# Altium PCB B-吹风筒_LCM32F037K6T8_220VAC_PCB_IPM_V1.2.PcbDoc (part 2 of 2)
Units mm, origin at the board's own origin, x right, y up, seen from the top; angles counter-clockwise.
Board outline 42.33 x 117.1 mm, 2 copper layers (TopLayer, BottomLayer); 131 components, 93 nets, 324 pads, 143 vias.
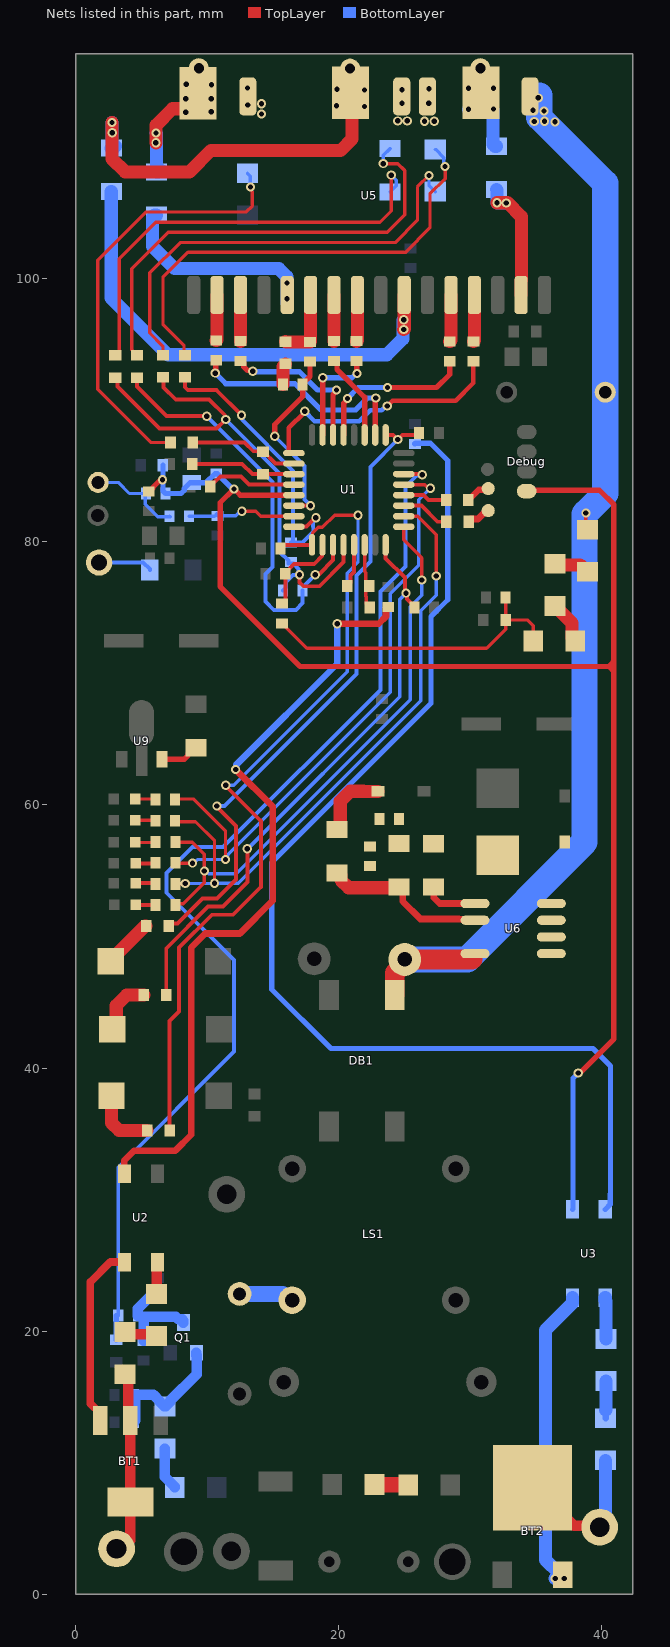
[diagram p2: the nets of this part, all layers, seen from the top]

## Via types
v1: diameter 0.7, hole 0.4, TopLayer to BottomLayer, tented both sides, 133 vias
v2: diameter 0.7, hole 0.4, TopLayer to BottomLayer, 10 vias

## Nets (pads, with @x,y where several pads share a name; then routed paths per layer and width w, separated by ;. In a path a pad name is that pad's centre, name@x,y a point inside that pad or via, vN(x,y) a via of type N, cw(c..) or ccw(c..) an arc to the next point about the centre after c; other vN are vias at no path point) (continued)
HV: C12.2 DB1.2 EC1.1 R44.2 U5.17 U6.4 | length 86.3
  TopLayer w0.254: v1(38.775,82.2) 38.775,81.05 R44.2@38.9,80.925
  TopLayer w1.5: DB1.2@24.25,45.55 24.25,47.225 25.006,47.981 EC1.1@25.006,48.251 30.126,48.251 30.15,48.275
  BottomLayer w2: EC1.1@25.006,48.251 29.751,48.251 38.675,57.175 38.675,82.1 v1(38.775,82.2) 40.25,83.675 C12.2@40.25,91.375 40.25,107.25 35.225,112.275 v1@35.225,113.925
  other v1: 36.425,111.925 34.85,111.95 35.625,111.975 35.6,112.75 34.75,112.8 35.15,113.75
IRbus: R16.2 R17.2 R20.2 R35.1 R38.1 R40.1 U5.22 | length 101
  TopLayer w0.25: R38.1@3,94.175 3.025,94.175 3.3,94.45 3.3,101.525 6.075,104.3 23.125,104.3 23.975,105.15 v1(23.975,107.875) ; R35.1@6.625,94.2 6.625,94.875 5.625,95.875 5.625,100.45 7.925,102.75 24.275,102.75 25.975,104.45 25.975,106.975 v1(26.85,107.85)
  TopLayer w0.254: R40.1@7.2,87.55 5.725,87.55 1.675,91.6 1.675,101.4 5.35,105.075 12.975,105.075 13.425,105.525 13.425,106.603 13.36,106.668 13.36,106.89 v1(13.275,106.975)
  BottomLayer w0.254: R20.2@13.05,108.025 13.275,107.8 v1(13.275,106.975) ; R16.2@23.9,106.6 24.368,107.068 24.368,107.482 v1(23.975,107.875) ; v1(26.85,107.85) 26.85,107.1 R17.2@27.325,106.625
  other v1: 14.125,112.525 13.075,113.2 14.125,113.3 13.05,114.5
IU: R17.1 R32.1 U5.19 | length 35.2
  TopLayer w0.254: R32.1@8.3,94.2 8.225,94.275 8.225,94.95 6.625,96.55 6.625,100.125 8.525,102.025 25.075,102.025 26.925,103.875 26.925,106.45 28.075,107.6 v1(28.075,108.525)
  BottomLayer w0.254: R17.1@27.325,109.825 27.355,109.825 27.978,109.202 27.978,108.743 28.075,108.646 v1(28.075,108.525)
  other v1: 26.5,111.975 27.25,111.975 26.825,113.35 26.85,114.45
IV: R16.1 R31.1 U5.20 | length 35.8
  TopLayer w0.254: R31.1@4.65,94.175 4.59,94.175 4.317,94.448 4.317,94.53 4.25,94.597 4.25,100.75 7.025,103.525 23.675,103.525 25,104.85 25,108.228 24.478,108.75 v1(23.375,108.75)
  BottomLayer w0.254: v1(23.375,108.75) 23.375,109.377 23.898,109.9 R16.1@23.9,109.9
  other v1: 24.475,112 25.2,112 24.8,113.35 24.8,114.375
K1: C30.1 R50.1 U1.25 | length 49.6
  TopLayer w0.3: R50.1@7.05,50.8 7.224,50.974 7.724,50.974 9.625,52.875 10.725,52.875 12.175,54.325 12.175,58.4 10.725,59.85 v1(10.725,59.921) ; U1.25@23.557,88.123 24.114,88.123 24.462,87.775 v1(24.475,87.775) 24.503,87.775 24.851,88.123 25.948,88.123 C30.1@26.1,88.275
  BottomLayer w0.3: v1(10.725,59.921) 11.296,59.921 21.325,69.95 21.325,77.425 22.4,78.5 22.4,85.7 v1(24.475,87.775)
K2: C26.1 R53.1 U1.9 | length 63.7
  TopLayer w0.25: U1.9@17.957,79.773 18.001,79.817 18.001,80.676 18.425,81.1 18.75,81.1 19.675,82.025 v1(21.45,82.025)
  TopLayer w0.3: R53.1@7.125,35.25 7.125,43.575 7.85,44.3 7.85,49.15 10.35,51.65 11.947,51.65 14.075,53.778 14.075,58.775 13.825,59.025 11.4,61.45 v1(11.4,61.5) ; C26.1@15.575,79.5 15.575,79.542 15.806,79.773 U1.9@17.957,79.773
  BottomLayer w0.25: v1(11.4,61.5) 12,61.5 20.625,70.125 20.625,77.625 21.45,78.45 v1(21.45,82.025)
K3: C28.1 R52.1 U1.16 | length 44.5
  TopLayer w0.3: R52.1@6.875,45.55 6.875,49.1 10.05,52.275 11.175,52.275 13.037,54.137 v1(13.037,56.663) ; U1.16@23.557,79.773 23.557,78.743 25.025,77.275 25.025,76.1 25.177,75.948 25.177,75.642 25.75,75.069 C28.1@25.75,75
  BottomLayer w0.3: v1(13.037,56.663) 13.062,56.663 24.625,68.225 24.625,75.625 v1(25.1,76.1)
LED1: R21.2 R26.2 U1.21 | length 48.2
  TopLayer w0.25: R26.2@7.316,55.925 7.572,55.669 R26.2@7.572,55.6 7.597,55.575 v1(8.875,55.575) ; U1.21@24.932,84.348 26.527,84.348 26.708,84.167 26.869,84.167 v1(26.955,84.081)
  TopLayer w0.254: R21.2@7.547,60.425 7.572,60.45 8.975,60.45 11.375,58.05 v1(11.375,55.85)
  BottomLayer w0.25: v1(8.875,55.575) 8.971,55.575 9.246,55.85 v1(11.375,55.85) 11.375,55.972 11.55,56.147 11.55,56.2 23.9,68.55 23.9,76.05 26.075,78.225 26.075,83.201 v1(26.955,84.081)
LED2: R22.2 R25.2 U1.18 | length 47.4
  TopLayer w0.25: R22.2@7.547,58.8 7.622,58.725 9.1,58.725 10.55,57.275 v1(10.55,54.048) ; R25.2@7.572,54 8.3,54 v1(8.325,54.025) ; U1.18@24.932,81.948 26.002,81.948 27.4,80.55 v1(27.4,77.4)
  BottomLayer w0.25: v1(8.325,54.025) 10.527,54.025 v1(10.55,54.048) 12.348,54.048 26.225,67.925 26.225,74.775 27.4,75.95 v1(27.4,77.4)
LED3: R23.2 R24.2 U1.17 | length 42.9
  TopLayer w0.254: R24.2@7.572,52.4 7.657,52.485 8.185,52.485 9.775,54.075 9.775,56.25 8.85,57.175 R23.2@7.572,57.175 ; U1.17@24.932,81.148 24.932,80.143 26.3,78.775 v1(26.3,77.1)
  BottomLayer w0.254: v1(9.775,54.975) 9.896,54.975 10.096,54.775 12.203,54.775 25.425,67.997 25.425,75.075 26.3,75.95 v1(26.3,77.1)
NetBT1_2: BT1.2 R12.1 负离子+.1 | length 14.1
  TopLayer w0.8: 负离子+.1@3.1,3.45 3.509,3.45 4.15,4.091 BT1.2@4.15,7.001 BT1.2@4.15,13.199 4,13.349 4,16.45 R12.1@3.725,16.725
NetBT1_3: BT1.3 U2.4 | length 15.4
  TopLayer w0.25: BT1.3@1.425,13.624 BT1.3@1.85,13.199 ; U2.4@3.325,24.675 3.7,25.05 U2.4@3.7,25.25
  TopLayer w0.6: BT1.3@1.85,13.199 1.85,13.749 1.1,14.499 1.1,23.725 2.625,25.25 U2.4@3.7,25.25
NetBT2_2: BT2.2 H1.1 R18.1 | length 11.6
  TopLayer w0.8: BT2.2@34.725,8.075 35,7.8 35.3,7.8 37.9,5.2 39.725,5.2 H1.1@39.825,5.1
  BottomLayer w1: H1.1@39.825,5.1 39.825,5.587 40.275,6.037 R18.1@40.275,10.175
NetBT2_3: BT2.3 U3.4 | length 23.7
  TopLayer w0.4: v1(36.45,1.2) 37.025,1.2 v1(37.125,1.2)
  BottomLayer w1: v1(36.45,1.2) v1(37.125,1.2) ; 36.788,1.538 35.7,2.625 35.7,20.075 37.75,22.125 U3.4@37.75,22.55
NetC1_2: C1.2 R1.2 U1.10 | length 6.7
  TopLayer w0.3: R1.2@15.675,75.297 15.728,75.297 15.959,75.528 15.959,77.681 16.603,78.325 18.125,78.325 18.723,78.923 18.723,79.739 U1.10@18.757,79.773
NetC2_2: C2.2 R60.1 | length 1.7
  TopLayer w1: C2.2@15.753,91.95 15.753,93.328 R60.1@15.95,93.525
NetC4_1: C4.1 C22.2 C33.1 D5.2 L1.2 R48.1 U6.5 U6.6 U6.7 U6.8
NetC4_2: C4.2 U6.1 | length 4.2
  TopLayer w0.5: C4.2@27.2,53.75 27.225,53.725 27.225,52.95 27.67,52.505 U6.1@30.348,52.505 U6.1@30.375,52.532
NetC8_2: C8.2 R7.2 U1.14 | length 5.2
  TopLayer w0.25: U1.14@21.957,79.773 21.957,77.743 22.05,77.65 22.05,76.925 R7.2@22.325,76.65 22.325,76.59 22.05,76.315 22.05,75.86 22.075,75.835 22.075,75.275 C8.2@22.35,75
NetC11_2: C11.2 U1.4 | length 7
  TopLayer w0.3: C11.2@10.222,84.2 10.222,84.269 10.453,84.5 10.522,84.5 10.997,84.975 12.55,84.975 13.177,84.348 U1.4@16.582,84.348
NetC13_1: C13.1 U5.12 | length 15.8
  BottomLayer w1: C13.1@6.125,104.825 5.975,104.825 5.825,104.675 5.825,102.475 7.525,100.775 15.425,100.775 16.052,100.148 16.052,98.475 16.052,98.125
  other v1: 16.05,98.475 16.05,99.675
NetC13_2: C13.2 pad.458 U5.23 W.1 | length 9.6
  TopLayer w1: v1(6.088,110.338) 6.1,110.35 v1(6.1,111.075) 6.1,111.675 7.35,112.925 9.3,112.925 9.3,113.859 W.1@9.3,114.1
  BottomLayer w1: v1(6.1,111.075) 6.125,111.05 C13.2@6.125,108.125 6.275,108.125 C13.2@6.425,108.275
  other v2: 8.35,112.65 10.3,112.7 8.35,113.675 10.3,113.675 10.325,114.75 8.4,114.775
NetC14_1: C14.1 U5.7 | length 36.6
  TopLayer w1: v1(24.925,96.15) 24.964,96.189 U5.7@24.964,98.759
  BottomLayer w1: C14.1@2.7,106.625 2.7,98.525 7,94.225 23.65,94.225 24.865,95.44 v1@24.865,96.875
  other v1: 24.925,96.875
NetC14_2: C14.2 pad.459 U5.21 V.1 | length 28.4
  TopLayer w1: v1(2.75,111.875) 2.75,111.1 2.75,109.125 3.75,108.125 8.65,108.125 10.275,109.75 20.125,109.75 21,110.625 21,112.925 20.875,113.05 20.875,113.859 V.1@20.875,114.15
  BottomLayer w1: v1(2.75,111.875) 2.75,109.975 C14.2@2.7,109.925 2.85,109.925 C14.2@3,110.075
  other v1: 2.775,111.1
  other v2: 21.95,113.1 19.825,113.15 21.95,114.35 19.85,114.4
NetC15_1: C15.1 Q1.3 R28.2 R30.1 | length 7.2
  BottomLayer w0.8: R30.1@4.725,21.175 4.725,21.7 5.553,22.528 R28.2@6.25,22.528 ; C15.1@5.15,19.25 5.15,20.181 5.15,20.719 ; 5.15,21.1 7.606,21.1 7.821,20.885 8.075,20.885 8.175,20.785 Q1.3@8.175,20.65
NetC18_1: C18.1 Q1.1 R34.2 R36.2 | length 10
  BottomLayer w0.8: R36.2@4.422,15.15 5.906,15.15 6.375,14.681 6.375,14.625 6.725,14.275 6.825,14.275 7.175,14.625 7.175,14.725 9.186,16.736 9.186,18.15 9.175,18.161 Q1.1@9.175,18.35 ; C18.1@4.425,13.075 4.425,13.123 4.525,13.223 R36.2@4.525,15.15
NetC22_1: C22.1 D4.2 R47.2 | length 5.5
  TopLayer w1: R47.2@19.85,58.125 19.95,58.125 20.1,58.275 20.1,60.275 20.861,61.036 21.883,61.036 21.894,61.025 D4.2@22.975,61.025
NetC29_1: C29.1 U5.2 | length 9.9
  TopLayer w1: v1(32.025,105.775) 32.825,105.775 33.875,104.725 33.875,99.876 33.854,99.856 U5.2@33.854,98.759
  BottomLayer w1: C29.1@31.975,106.775 32.025,106.725 v1(32.025,105.775) ; v1@32.15,105.75 v1(32.725,105.75)
NetC29_2: C29.2 pad.460 U5.18 U.1 | length 10
  TopLayer w0.254: v1(29.85,112.875) 30.8,113.825 U5.18@30.8,113.85 ; v1(29.85,114.475) 30.475,113.85 U5.18@30.8,113.85 ; v1(31.75,112.9) U5.18@30.8,113.85 ; v1(31.75,114.475) 31.425,114.475 U5.18@30.8,113.85
  BottomLayer w1: v1(29.85,112.875) v1@31.724,112.875 ; v1@31.725,112.876 31.725,110.225 31.875,110.075 C29.2@31.975,110.075
NetC33_2: C33.2 R47.1 R48.2 U6.2 | length 12.6
  TopLayer w0.5: R48.2@24.5,53.7 24.532,53.7 24.857,53.375 24.857,52.668 26.2,51.325 29.106,51.325 29.119,51.312 29.38,51.312 29.418,51.273 30.31,51.273 U6.2@30.348,51.235
  TopLayer w1: R47.1@19.85,54.825 20,54.675 20.15,54.675 20.15,54.286 20.736,53.7 R48.2@24.5,53.7
NetCY1_1: CY1.1 CY2.1 | length 4.1
  BottomLayer w0.3: CY1.1@1.775,78.425 5.125,78.425 5.625,77.925 CY2.1@5.625,77.875
NetLED1_1: LED1.1 R21.1 | length 1.5
  TopLayer w0.25: LED1.1@4.525,60.45 6.025,60.45 R21.1@6.05,60.425
NetLED2_1: LED2.1 R22.1 | length 1.5
  TopLayer w0.25: LED2.1@4.525,58.825 6.025,58.825 R22.1@6.05,58.8
NetLED3_1: LED3.1 R23.1 | length 1.6
  TopLayer w0.25: LED3.1@4.525,57.15 6.05,57.15 R23.1@6.075,57.175
NetLED4_1: LED4.1 R24.1 | length 1.5
  TopLayer w0.3: LED4.1@4.575,52.4 R24.1@6.075,52.4
NetLED5_1: LED5.1 R25.1 | length 1.5
  TopLayer w0.3: LED5.1@4.55,54.05 6.025,54.05 R25.1@6.075,54
NetLED6_1: LED6.1 R26.1 | length 1.5
  TopLayer w0.3: LED6.1@4.55,55.55 6.025,55.55 R26.1@6.075,55.6
NetLS1_2: LS1.2 NTC1.2 | length 4.2
  BottomLayer w1.2: NTC1.2@12.45,22.825 15.731,22.825 16.206,22.35 LS1.2@16.45,22.35
NetR2_1: R2.1 U5.10 | length 3.5
  TopLayer w1: R2.1@19.625,95.25 19.63,95.255 U5.10@19.63,98.759
NetR3_1: R3.1 U5.14 | length 3.5
  TopLayer w1: U5.14@12.518,98.759 12.518,98.103 12.525,98.096 R3.1@12.525,95.25
NetR6_1: R6.1 U5.9 | length 3.5
  TopLayer w1: R6.1@21.35,95.25 21.408,95.308 U5.9@21.408,98.759
NetR8_1: R8.1 R60.2 U5.11 | length 5.4
  TopLayer w1: R60.2@15.95,95.225 15.975,95.2 R8.1@17.8,95.2 17.852,95.252 U5.11@17.852,98.759
NetR9_1: R9.1 TX.1 | length 1.9
  TopLayer w0.5: R9.1@29.85,83.175 29.85,83.235 30,83.385 30.06,83.385 30.629,83.954 31.254,83.954 TX.1@31.35,84.05
NetR10_1: R10.1 RX.1 | length 1.9
  TopLayer w0.5: R10.1@29.875,81.525 29.875,81.585 30.025,81.735 30.575,81.735 31.215,82.375 RX.1@31.35,82.375
NetR11_1: R11.1 U5.4 | length 3.6
  TopLayer w1: R11.1@30.225,95.225 30.298,95.298 U5.4@30.298,98.759
NetR12_2: R12.2 R14.1 | length 2.5
  TopLayer w0.8: R12.2@3.725,19.925 3.875,19.775 5.975,19.775 R14.1@6.125,19.625
NetR13_1: R13.1 U5.5 | length 3.6
  TopLayer w1: R13.1@28.425,95.225 28.52,95.32 U5.5@28.52,98.759
NetR14_2: R14.2 U2.3 | length 2.5
  TopLayer w0.8: R14.2@6.125,22.825 6.162,22.862 6.162,25.212 U2.3@6.2,25.25
NetR15_2: R15.2 U2.2 | length 59
  TopLayer w0.5: U2.2@3.7,31.95 3.675,31.975 3.675,32.95 4.45,33.725 7.575,33.725 8.775,34.925 8.775,49.156 9.847,50.228 12.478,50.228 14.975,52.725 14.975,59.875 v1(12.15,62.7) ; v1(19.875,73.775) 23.025,73.775 23.581,74.331 23.581,74.922 23.712,75.053 R15.2@23.75,75.053
  BottomLayer w0.5: v1(12.15,62.7) 12.188,62.738 12.188,63.038 19.875,70.725 v1(19.875,73.775)
NetR18_2: R18.2 R19.1 | length 2.8
  BottomLayer w0.5: R18.2@40.275,13.375 R18.2@40.275,14
  BottomLayer w1: R18.2@40.275,14 40.3,14.025 R19.1@40.3,16.2
NetR19_2: R19.2 U3.3 | length 3.2
  BottomLayer w1: U3.3@40.25,22.55 40.25,22.35 40.3,22.3 R19.2@40.3,19.4
NetR27_1: R27.1 U5.15 | length 3.5
  TopLayer w1: R27.1@10.675,95.3 10.74,95.365 U5.15@10.74,98.759
NetR29_2: R29.2 U3.2 | length 88
  BottomLayer w0.4: R29.2@25.775,87.453 25.822,87.5 26.946,87.5 28.275,86.171 28.275,75.6 27,74.325 27,67.725 14.9,55.625 14.9,45.975 19.4,41.475 39.325,41.475 40.65,40.15 40.65,30.458 40.623,30.431 40.623,29.623 U3.2@40.25,29.25
NetR33_1: R33.1 R37.1 S1.2 | length 7.2
  BottomLayer w0.25: S1.2@1.7,84.517 3.233,84.517 4.075,83.675 R33.1@5.325,83.675 5.275,83.625 5.275,82.85 6.228,81.897 7.075,81.897 R37.1@7.125,81.947 R37.1@7.175,81.897
NetR34_1: R34.1 R39.2 | length 3.3
  BottomLayer w0.8: R34.1@6.775,11.075 6.775,8.925 7.525,8.175 R39.2@7.525,8.125
NetR41_1: R41.1 R45.2 | length 3.3
  TopLayer w1: R41.1@36.425,75.125 36.475,75.125 36.725,74.875 36.725,74.825 37.725,73.825 37.725,72.7 R45.2@37.975,72.45
NetR41_2: R41.2 R44.1 | length 2.7
  TopLayer w1: R41.2@36.425,78.325 36.507,78.243 38.332,78.243 38.85,77.725 R44.1@38.9,77.725
NetR43_2: R43.2 R46.1 | length 2.6
  TopLayer w1.2: R46.1@22.7,8.35 22.725,8.325 25.25,8.325 R43.2@25.275,8.3
NetR49_2: R49.2 U9.1 | length 3
  TopLayer w0.4: U9.1@6.549,63.48 8.255,63.48 8.525,63.75 8.525,63.9 8.975,64.35 R49.2@9.125,64.35
NetR50_2: R50.2 S5.1 | length 3.8
  TopLayer w1: S5.1@2.661,48.125 3.161,48.625 3.161,48.686 5.275,50.8 R50.2@5.35,50.8
NetR52_2: R52.2 S4.1 | length 4.4
  TopLayer w1: S4.1@2.761,42.95 3.078,43.268 3.078,44.753 3.875,45.55 R52.2@5.175,45.55
NetR53_2: R53.2 S3.1 | length 5
  TopLayer w1: S3.1@2.711,37.9 2.711,35.836 3.296,35.25 R53.2@5.425,35.25
NTC1: C19.2 R37.2 U1.7 | length 8.3
  TopLayer w0.25: v1(12.625,82.325) 13.675,82.325 14.052,81.948 U1.7@16.582,81.948
  BottomLayer w0.254: R37.2@8.622,81.947 10.55,81.947 C19.2@10.726,82.123 ; C19.2@10.775,81.975 12.154,81.975 12.504,82.325 v1(12.625,82.325)
OPA0N/OPA2N: C16.2 C17.2 R35.2 R38.2 U1.12 | length 39.7
  TopLayer w0.3: R38.2@3,92.475 3.174,92.301 3.174,91.801 6.375,88.6 10.7,88.6 v1(11.4,89.3) 11.323,89.377 11.323,89.627 10.125,90.825 7.6,90.825 6.678,91.747 6.678,92.447 R35.2@6.625,92.5 ; v1(17.001,77.504) 17.001,76.924 17.3,76.625 18.525,76.625 20.357,78.457 U1.12@20.357,79.773
  BottomLayer w0.3: v1(11.4,89.3) 15.5,85.2 15.5,79.234 16.164,78.57 16.164,78.336 16.536,78.336 16.924,77.948 16.924,77.58 v1(17.001,77.504) 16.971,77.474 16.499,77.474 15.973,76.948 15.973,76.52 C17.2@15.753,76.3
OPA0P: C16.1 R32.2 U1.8 | length 22.4
  TopLayer w0.3: R32.2@8.3,92.5 8.3,91.75 8.525,91.525 10.7,91.525 v1(12.6,89.625) ; U1.8@16.582,81.148 16.601,81.167 17.542,81.167 18.2,81.825 v1(18.25,81.825)
  BottomLayer w0.3: v1(12.6,89.625) 12.677,89.548 12.677,89.248 16.525,85.4 C16.1@16.525,79.951 ; C16.1@16.35,79.95 16.526,79.95 17.225,79.95 18.05,80.775 18.05,81.17 18.045,81.176 18.045,81.511 18.25,81.717 v1(18.25,81.825)
OPA1_OUT: R7.1 U1.13 | length 3.3
  TopLayer w0.3: R7.1@20.625,76.65 20.875,76.9 20.875,77.425 21.157,77.707 U1.13@21.157,79.773
OPA1N: C21.2 R42.2 U1.3 | length 8.1
  TopLayer w0.3: R42.2@8.85,85.925 12.65,85.925 13.425,85.15 C21.2@14.225,85.15 14.226,85.149 16.581,85.149 U1.3@16.582,85.148
OPA1P: C21.1 R40.2 U1.2 | length 8.3
  TopLayer w0.3: R40.2@8.9,87.55 12.825,87.55 13.491,86.884 14.251,86.884 15.187,85.948 U1.2@16.582,85.948
OPA2P: C17.1 R31.2 U1.11 | length 31.6
  TopLayer w0.3: R31.2@4.649,92.474 4.649,91.801 6.9,89.55 v1(9.95,89.55) ; v1(18.2,77.494) 18.277,77.57 18.52,77.57 19.557,78.607 U1.11@19.557,79.773
  BottomLayer w0.3: v1(9.95,89.55) 14.95,84.55 14.95,78.075 14.425,77.55 14.425,75.45 15.05,74.825 16.725,74.825 17.25,75.35 C17.1@17.25,76.3 ; 17.46,76.754 v1(18.2,77.494)
RXD: R10.2 U1.19 | length 3.7
  TopLayer w0.3: U1.19@24.932,82.748 26.277,82.748 27.5,81.525 R10.2@28.175,81.525
TEMP: C2.1 R8.2 U1.6 | length 14.5
  TopLayer w0.3: U1.6@16.525,82.748 U1.6@16.582,82.748 17.848,82.748 v1(17.85,82.75)
  TopLayer w0.4: v1(15.125,88.025) 15.125,88.925 17.25,91.05 C2.1@17.25,91.95 17.25,92.019 17.8,92.569 R8.2@17.8,93.703
  BottomLayer w0.3: v1(15.125,88.025) 17.375,85.775 17.375,83.225 v1(17.85,82.75)
TXD: R9.2 U1.20 | length 3.4
  TopLayer w0.3: U1.20@24.932,83.548 26.427,83.548 26.8,83.175 R9.2@28.15,83.175
UH: R11.2 U1.1 | length 20
  TopLayer w0.35: U1.1@16.582,86.748 16.26,86.748 16.2,86.808 16.2,88.663 17.4,89.863 v1(17.4,89.925) ; v1(23.675,90.325) 24.075,90.725 28.875,90.725 30.225,92.075 R11.2@30.225,93.728
  BottomLayer w0.35: v1(17.4,89.925) 18.15,89.175 21.55,89.175 22.375,90 23.255,90 23.58,90.325 v1(23.675,90.325)
UL: R13.2 U1.29 | length 12.4
  TopLayer w0.4: U1.29@20.357,88.123 20.372,88.138 20.372,88.78 20.375,88.783 20.375,90.544 20.65,90.819 v1(20.65,90.9) ; v1(23.7,91.725) 27.425,91.725 28.425,92.725 R13.2@28.425,93.728
  BottomLayer w0.4: v1(20.65,90.9) 21.475,91.725 v1(23.7,91.725)
Vdc: C24.1 R1.1 R4.2 R45.1 | length 24.3
  TopLayer w0.25: R1.1@15.675,73.8 15.744,73.8 16,73.544 16,73.475 17.575,71.9 31.225,71.9 32.675,73.35 C24.1@32.675,74.05 ; R4.2@32.672,75.775 32.675,75.772 C24.1@32.675,74.05 ; R45.1@34.775,72.45 34.775,73.625 34.35,74.05 C24.1@32.675,74.05
VDDA: C7.1 C9.1 C10.2 Debug.1 R5.1 R33.2 U1.5 U3.1 | length 119.4
  TopLayer w0.254: 40.85,69.775 ccw(c40.162,69.837) 40.225,70.525 ccw(c40.162,71.213) 40.85,71.275
  TopLayer w0.4: R5.1@5.55,83.825 5.619,83.825 5.875,84.081 5.875,84.15 6.364,84.639 6.514,84.639 v1(6.6,84.725) ; U1.5@16.582,83.548 12.502,83.548 v1(12.025,84.025) 10.975,82.975 10.975,76.6 17.05,70.525 40.9,70.525 ; Debug.1@34.275,83.85 34.35,83.925 39.8,83.925 40.9,82.825 40.9,70.525 ; v1(38.2,39.625) 38.322,39.625 38.522,39.825 38.525,39.825 40.9,42.2 40.9,70.525
  BottomLayer w0.4: C7.1@6.625,85.825 6.625,83.872 R33.2@6.822,83.675 8,83.675 8.25,83.925 8.25,84.05 8.7,84.5 C9.1@8.825,84.5 9.903,84.5 10.606,85.203 10.744,85.203 11.922,84.025 v1(12.025,84.025) ; U3.1@37.75,29.25 37.8,29.3 37.8,39.225 v1(38.2,39.625)
VH: R6.2 U1.31 | length 8.1
  TopLayer w0.4: U1.31@18.757,88.123 18.772,88.138 18.772,88.78 18.775,88.783 18.775,90.637 18.768,90.645 18.768,91.307 18.775,91.315 v1(18.775,92.475) ; R6.2@21.35,93.753 21.361,93.742 21.361,92.814 v1(21.371,92.804)
  BottomLayer w0.4: v1(18.775,92.475) 20.987,92.475 21.316,92.804 v1(21.371,92.804)
VL: R2.2 U1.27 | length 6.6
  TopLayer w0.4: R2.2@19.625,93.753 19.806,93.572 19.851,93.572 19.851,93.099 21.957,90.993 U1.27@21.957,88.123
WH: R3.2 U1.30 | length 11.9
  TopLayer w0.4: R3.2@12.525,93.753 12.594,93.753 12.775,93.572 12.775,93.297 13.055,93.017 13.393,93.017 v1(13.45,92.959) ; U1.30@19.557,88.123 19.557,91.201 19.825,91.469 v1(19.825,91.55)
  BottomLayer w0.4: v1(13.45,92.959) 13.484,92.925 17,92.925 18.375,91.55 v1(19.825,91.55)
WL: R27.2 U1.26 | length 17.6
  TopLayer w0.4: v1(10.6,92.825) 10.637,92.863 10.637,93.765 R27.2@10.675,93.803 ; U1.26@22.757,88.123 22.757,90.882 v1(22.8,90.925)
  BottomLayer w0.4: v1(10.6,92.825) 11.4,92.025 16.65,92.025 18.65,90.025 21.275,90.025 22.175,90.925 v1(22.8,90.925)
ZERO: C5.1 R30.2 U1.22 | length 82.6
  TopLayer w0.3: U1.22@24.932,85.148 24.957,85.173 26.261,85.173 v1(26.332,85.102)
  BottomLayer w0.3: R30.2@3.228,21.175 3.228,32.453 12.025,41.25 12.025,48.2 6.9,53.325 6.9,54.825 8.425,56.35 8.875,56.8 11.2,56.8 23.15,68.75 23.15,76.225 25.05,78.125 25.05,84.161 25.915,85.025 26.256,85.025 v1(26.332,85.102)
  BottomLayer w0.4: C5.1@3.075,19.35 R30.2@3.075,21.175
pads on no net: U5.6 U5.16

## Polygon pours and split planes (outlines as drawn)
GND on BottomLayer "Top Layer-No Net" (solid, remove dead copper, pour order 20): 7.6,73.65 4.5,76.75 4.5,86.975 9.35,91.825 26.925,91.825 30.15,88.6 30.15,72.95 29.2,72 9.25,72
NetC29_2 on BottomLayer "Top Layer-No Net" (solid, remove dead copper, pour order 29): 29.65,116.7 29.325,116.375 29.325,112.55 29.625,112.25 29.65,112.275 31.9,112.275 32.175,112.55 32.175,116.375 31.85,116.7
NetC13_2 on BottomLayer "Top Layer-No Net" (solid, remove dead copper, pour order 28): 8.25,116.7 7.925,116.375 7.925,112.55 8.225,112.25 8.25,112.275 10.5,112.275 10.775,112.55 10.775,116.375 10.45,116.7
NetC14_2 on BottomLayer "Top Layer-No Net" (solid, remove dead copper, pour order 27): 19.75,116.675 19.425,116.35 19.425,112.525 19.725,112.225 19.75,112.25 22,112.25 22.275,112.525 22.275,116.35 21.95,116.675
IRbus on BottomLayer "Top Layer-No Net" (solid, remove dead copper, pour order 7): 27.75,107.525 27.725,107.55 17.925,107.55 14.95,110.525 14.95,114.775 14.575,115.15 12.725,115.15 12.4,114.825 12.4,107.55 12.9,107.05 13.925,107.05 15.5,105.475 28.225,105.475 28.425,105.675 28.425,107.325 28.225,107.525
GND on BottomLayer "Top Layer-No Net" (solid, remove dead copper, pour order 8): 12.25,105.875 12.275,105.9 13.775,105.9 15,104.675 29.975,104.675 35.675,104.675 36.525,103.825 36.525,97.8 36.15,97.425 35.275,97.425 34.925,97.775 34.925,99.625 32.775,101.775 28.7,101.775 27.975,102.5 12.425,102.5 11.5,103.425 11.5,105.325 12.05,105.875
IU on BottomLayer "Top Layer-No Net" (solid, remove dead copper, pour order 6): 26.1,109.25 26.275,109.075 28.15,109.075 28.35,109.275 28.35,111.45 27.6,112.2 27.6,114.525 27.325,114.8 26.35,114.8 26.1,114.55
IV on BottomLayer "Top Layer-No Net" (solid, remove dead copper, pour order 5): 24.075,112.2 22.875,111 22.875,109.35 23.05,109.175 25.425,109.175 25.625,109.375 25.625,114.5 25.375,114.75 24.325,114.75 24.075,114.5
GND on TopLayer "Top Layer-No Net" (solid, remove dead copper, pour order 19): 7.65,73 7.625,73.025 7.625,73.65 6.45,74.825 6.45,79.25 4.875,80.825 0.925,80.825 0.925,80.85 0.375,81.4 0.375,82.575 1,83.2 5.75,83.2 12.75,90.2 30.675,90.2 35.1,85.775 35.1,81.875 31.75,78.525 31.75,73.525 30.6,72.375 19.275,72.375 16.575,75.075 14.875,75.075 12.84,73.04
HV on TopLayer "Top Layer-No Net" (solid, remove dead copper, pour order 25): 33.975,115.4 33.8,115.225 33.8,112 34.275,111.525 36.525,111.525 36.775,111.775 36.775,115.125 36.5,115.4
IU on TopLayer "Top Layer-No Net" (solid, remove dead copper, pour order 24): 26.225,115.65 26.075,115.5 26.075,111.75 26.25,111.575 27.475,111.575 27.625,111.725 27.625,115.45 27.425,115.65
IV on TopLayer "Top Layer-No Net" (solid, remove dead copper, pour order 23): 24.25,115.65 24.05,115.45 24.05,111.825 24.3,111.575 25.375,111.575 25.55,111.75 25.525,111.775 25.525,115.45 25.325,115.65
IRbus on TopLayer "Top Layer-No Net" (solid, remove dead copper, pour order 22): 12.575,115.675 12.4,115.5 12.4,112.275 12.575,112.1 14.75,112.1 14.925,112.275 14.925,115.45 14.7,115.675
GND on TopLayer "Top Layer-No Net" (solid, remove dead copper, pour order 21): 9.75,49.25 9.625,49.125 9.625,37.1 9.9,36.825 12.1,36.825 12.575,37.3 14.35,37.3 14.625,37.575 14.625,49 14.375,49.25
GND on TopLayer "Top Layer-No Net" (solid, remove dead copper, pour order 18): 7.625,73.15 3.875,69.4 3.875,65.125 4.425,64.575 4.425,62.35 4.75,62.025 4.775,62.05 5.25,62.05 5.575,62.375 5.55,62.4 5.55,64.45 6.175,65.075 6.175,67.775 9.825,71.425 10.975,71.425 11.375,71.825 11.375,72.8 11.025,73.15
GND on TopLayer "Top Layer-No Net" (solid, remove dead copper, pour order 15): 37.775,66.7 35.075,66.7 34.45,66.075 34.45,60.475 35.175,59.75 38.8,59.75 39.55,60.5 39.55,65.975 38.825,66.7
NetC4_1 on TopLayer "Top Layer-No Net" (solid, remove dead copper, pour order 14): 33.175,58.3 38.825,58.3 39.125,58 39.125,48.8 38.45,48.125 35.2,48.125 34.475,48.85 34.475,54.025 33.625,54.875 33.625,55.3
15V on TopLayer "Top Layer-No Net" (solid, remove dead copper, pour order 13): 26.175,66.675 25.725,66.225 25.725,60.4 26.125,60 33.375,60 33.875,60.5 33.875,66.05 33.25,66.675
NetC33_2 on TopLayer "Top Layer-No Net" (solid, remove dead copper, pour order 12): 19.175,55.825 18.925,55.575 18.925,53.225 19.2,52.95 25.825,52.95 25.975,53.1 25.975,55.7 25.85,55.825
NetC4_1 on TopLayer "Top Layer-No Net" (solid, remove dead copper, pour order 11): 24.175,59.35 24.1,59.275 24.1,58.325 23.25,57.475 21.8,57.475 21.525,57.2 21.525,56.625 21.925,56.225 28.3,56.225 29.925,54.6 33.9,54.6 34.125,54.825 34.125,58 33.825,58.3 29.475,58.3 28.425,59.35
NetC22_1 on TopLayer "Top Layer-No Net" (solid, remove dead copper, pour order 9): 22.75,62.45 19.7,62.45 18.775,61.525 18.775,57.55 19.275,57.05 20.575,57.05 21.7,58.175 23.275,58.175 23.675,58.575 23.675,61.9 23.125,62.45

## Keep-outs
KeepOutLayer:
  circle w0.127: c32.925,33.5 r1.5
  circle w0.127: c39.566,114.428 r1.5
  circle w0.127: c2.65,114.875 r1.5
  lines w0.127: 0,0 0,117.1 41,117.1 42.4,117.1 42.4,0 0,0
  lines w1: 5.675,1.25 5.675,4.425 7.225,5.975 12.875,5.975 ; 8.15,30.7 12.324,34.823 16.175,34.8 ; 9.325,10.4 9.325,13.775 10.55,15 10.55,18.05 ; 10.3,27.7 16.05,27.7 ; 10.625,23.925 10.65,21.25 ; 11.55,19.4 17.925,19.375 ; 11.625,111.9 11.625,116.15 ; 13.9,24.7 28.45,24.7 ; 17.425,1 17.425,3.7 ; 21.65,43.1 21.65,49.175 ; 21.775,32 21.775,37.55 ; 22.25,1.075 22.25,3.65 ; 23.3,112.4 23.3,115.75 ; 24.25,50.225 28.65,50.225 ; 28.425,112.3 28.425,115.55 ; 30.475,10.55 30.475,3.85 31.05,3.275 ; 33.1,112.15 33.1,115.625 ; 33.9,12.525 33.9,23.125 ; 36.675,26.1 41.075,26.1 ; 37.85,95.85 37.85,105.65

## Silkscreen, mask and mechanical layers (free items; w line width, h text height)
TopOverlay:
  drawing of 1979 lines, arcs and shapes, not listed
  text "NTC" at 1.95,102.092 h1.52
  text "CLK" at 35.8,88.038 h1.2
  text "DIO" at 35.8,86.513 h1.2
  text "GND" at 35.8,85.038 h1.2
  text "5V" at 35.975,83.588 h1.2
  text "-" at 14.75,34.612 h5
  text "+" at 27.275,34.107 h5
  text "吹风筒_LCM32F037_IPM_V1.2" at 32.051,30.492 h0.8
  text "2022.6.30" at 36.124,29.184 h0.8
  text "电热丝+" at 37.775,1.696 h1.52
BottomOverlay:
  lines w0.127: 34.575,4.975 34.575,1.9 41.2,1.9 ; 34.65,4.975 34.8,4.975 ; 34.725,4.975 41.225,4.975 41.225,1.925
  text "开关机" at 8.814,47.81 h1.52
  text "风量档位" at 9.421,42.435 h1.52
  text "加热" at 8.066,37.447 h1.52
